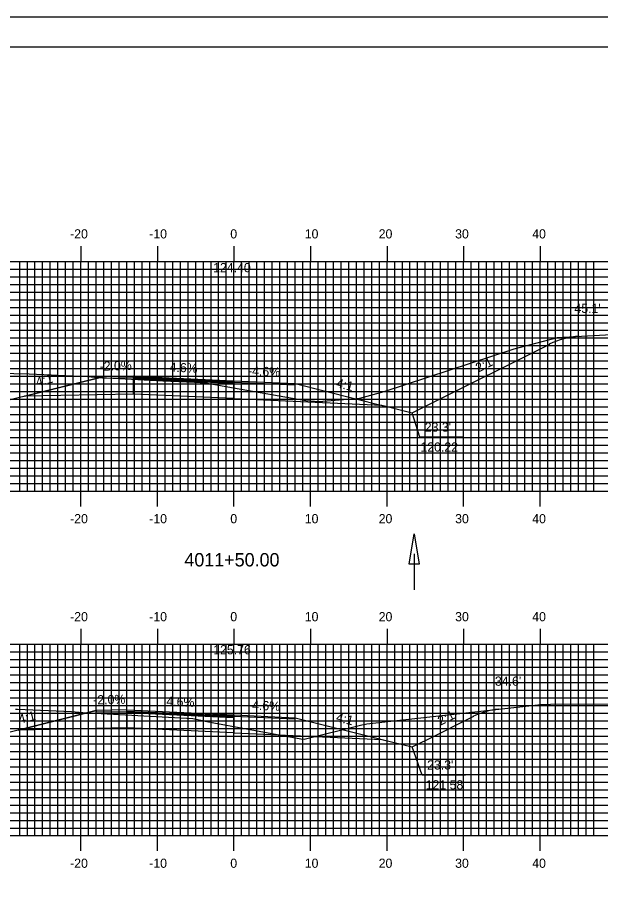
# Model space of a CAD drawing. Extents: x 852540 to 852884, y 364661 to 364881.
# Drawn here: x 852678 to 852754.2, y 364768.2 to 364881.3 of the extents above; entities that cross this region are included whole.
import ezdxf

# ---------------------------------------------------------------- set-up
doc = ezdxf.new("R2010")
doc.units = 0
for name, color, linetype in [('ANNOTATION', 7, 'Continuous'), ('BORDER', 7, 'Continuous'), ('D_Drainage_Ditch_Line', 7, 'Continuous'), ('D_Roadway_Centerline_Text', 7, 'Continuous'), ('D_Roadway_Edge_Shoulder', 7, 'Continuous'), ('D_Roadway_Edge_TW', 7, 'Continuous'), ('D_Roadway_Pavement', 7, 'Continuous'), ('D_Roadway_SlopeLines', 7, 'Continuous'), ('D_Roadway_SubGrade', 7, 'Continuous'), ('D_Text_Standard', 7, 'Continuous'), ('H_V ANNOTATION', 7, 'Continuous'), ('M_Roadway_Centerline', 7, 'Continuous'), ('MAJOR', 7, 'Continuous'), ('MINOR', 7, 'Continuous'), ('PLOT BOUNDARY', 7, 'Continuous'), ('S_Roadway_Centerline', 7, 'Continuous')]:
    doc.layers.add(name, color=color, linetype=linetype)

msp = doc.modelspace()

# ---------------------------------------------------------------- linework, layer by layer
at = {"layer": 'ANNOTATION'}
for points in [[(852725.57, 364830.59), (852729.57, 364829.59), (852731.57, 364830.59), (852747.53, 364838.57)], [(852736.23, 364826.4), (852730.54, 364826.4), (852729.57, 364829.59)], [(852725.57, 364786.95), (852729.57, 364785.95), (852731.57, 364786.95), (852737.6, 364789.97)], [(852736.54, 364782.29), (852730.85, 364782.29), (852729.57, 364785.95)]]:
    msp.add_lwpolyline(points, dxfattribs=at)
at = {"layer": 'BORDER'}
msp.add_lwpolyline([(852556.67, 364667.37), (852876.67, 364667.37), (852876.67, 364877.37), (852556.67, 364877.37)], close=True, dxfattribs=at)
at = {"layer": 'D_Drainage_Ditch_Line'}
msp.add_line((852729.82, 364811.16), (852729.82, 364806.46), dxfattribs=at)
msp.add_lwpolyline([(852730.47, 364809.84), (852729.16, 364809.84), (852729.82, 364813.78)], close=True, dxfattribs=at)
at = {"layer": 'D_Roadway_Edge_Shoulder'}
for points in [[(852693.13, 364834.39), (852689.13, 364834.31), (852689.13, 364834.14), (852693.13, 364834.21)], [(852692.28, 364790.79), (852688.28, 364790.71), (852688.28, 364790.54), (852692.28, 364790.6)]]:
    msp.add_lwpolyline(points, close=True, dxfattribs=at)
at = {"layer": 'D_Roadway_Edge_TW'}
for p, q in [((852706.27, 364833.79), (852714.27, 364833.42)), ((852706.27, 364790.14), (852714.27, 364789.78))]:
    msp.add_line(p, q, dxfattribs=at)
for points in [[(852693.13, 364834.39), (852706.27, 364833.79), (852706.27, 364833.62), (852693.13, 364834.21)], [(852692.28, 364790.79), (852706.27, 364790.14), (852706.27, 364789.98), (852692.28, 364790.6)]]:
    msp.add_lwpolyline(points, close=True, dxfattribs=at)
for points in [[(852706.27, 364833.62), (852714.27, 364833.25), (852714.27, 364833.42)], [(852706.27, 364789.98), (852714.27, 364789.61), (852714.27, 364789.78)]]:
    msp.add_lwpolyline(points, dxfattribs=at)
at = {"layer": 'D_Roadway_Pavement'}
for points in [[(852693.13, 364834.21), (852706.27, 364833.62), (852706.27, 364833.45), (852693.13, 364834.04)], [(852692.28, 364790.6), (852706.27, 364789.98), (852706.27, 364789.81), (852692.28, 364790.44)]]:
    msp.add_lwpolyline(points, close=True, dxfattribs=at)
for points in [[(852693.13, 364834.21), (852693.13, 364834.04)], [(852706.27, 364833.62), (852706.27, 364833.45)], [(852706.27, 364833.62), (852706.27, 364833.45)], [(852692.28, 364790.6), (852692.28, 364790.44)], [(852706.27, 364789.98), (852706.27, 364789.81)], [(852706.27, 364789.98), (852706.27, 364789.81)]]:
    msp.add_lwpolyline(points, dxfattribs=at)
at = {"layer": 'D_Roadway_SlopeLines'}
for points in [[(852689.13, 364834.31), (852674.91, 364830.76)], [(852714.27, 364833.42), (852725.8, 364830.53)], [(852688.28, 364790.71), (852674.06, 364787.15)], [(852714.27, 364789.78), (852725.8, 364786.89)]]:
    msp.add_lwpolyline(points, dxfattribs=at)
for centre, start in [((852751.94, 364829.6), 93.165), ((852741.96, 364780.97), 96.3976)]:
    msp.add_arc(centre, 10, start, 116.5651, dxfattribs=at)
at = {"layer": 'D_Roadway_SubGrade'}
for p, q in [((852706.27, 364831.45), (852725.57, 364830.59)), ((852706.27, 364787.81), (852725.57, 364786.95))]:
    msp.add_line(p, q, dxfattribs=at)
for points in [[(852693.13, 364832.04), (852678.91, 364831.76), (852689.13, 364834.31), (852689.13, 364834.14), (852693.13, 364834.21), (852693.13, 364834.04)], [(852693.13, 364834.04), (852706.27, 364833.45), (852706.27, 364831.45), (852693.13, 364832.04)], [(852692.28, 364788.44), (852678.06, 364788.15), (852688.28, 364790.71), (852688.28, 364790.54), (852692.28, 364790.6), (852692.28, 364790.44)], [(852692.28, 364790.44), (852706.27, 364789.81), (852706.27, 364787.81), (852692.28, 364788.44)]]:
    msp.add_lwpolyline(points, close=True, dxfattribs=at)
at = {"layer": 'MAJOR'}
for p, q in [((852686.27, 364851.37), (852686.27, 364849.37)), ((852696.27, 364851.37), (852696.27, 364849.37)), ((852706.27, 364851.37), (852706.27, 364849.37)), ((852716.27, 364851.37), (852716.27, 364849.37)), ((852726.27, 364851.37), (852726.27, 364849.37)), ((852736.27, 364851.37), (852736.27, 364849.37)), ((852746.27, 364851.37), (852746.27, 364849.37)), ((852566.27, 364849.37), (852846.27, 364849.37)), ((852566.27, 364849.37), (852846.27, 364849.37)), ((852686.27, 364819.37), (852686.27, 364849.37)), ((852696.27, 364819.37), (852696.27, 364849.37)), ((852706.27, 364819.37), (852706.27, 364849.37)), ((852716.27, 364819.37), (852716.27, 364849.37)), ((852726.27, 364819.37), (852726.27, 364849.37)), ((852736.27, 364819.37), (852736.27, 364849.37)), ((852746.27, 364819.37), (852746.27, 364849.37)), ((852566.27, 364844.37), (852846.27, 364844.37)), ((852566.27, 364839.37), (852846.27, 364839.37)), ((852566.27, 364834.37), (852846.27, 364834.37)), ((852566.27, 364829.37), (852846.27, 364829.37)), ((852566.27, 364824.37), (852846.27, 364824.37)), ((852566.27, 364819.37), (852846.27, 364819.37)), ((852566.27, 364819.37), (852846.27, 364819.37)), ((852686.27, 364817.37), (852686.27, 364819.37)), ((852696.27, 364817.37), (852696.27, 364819.37)), ((852706.27, 364817.37), (852706.27, 364819.37)), ((852716.27, 364817.37), (852716.27, 364819.37)), ((852726.27, 364817.37), (852726.27, 364819.37)), ((852736.27, 364817.37), (852736.27, 364819.37)), ((852746.27, 364817.37), (852746.27, 364819.37)), ((852686.27, 364801.37), (852686.27, 364799.37)), ((852696.27, 364801.37), (852696.27, 364799.37)), ((852706.27, 364801.37), (852706.27, 364799.37)), ((852716.27, 364801.37), (852716.27, 364799.37)), ((852726.27, 364801.37), (852726.27, 364799.37)), ((852736.27, 364801.37), (852736.27, 364799.37)), ((852746.27, 364801.37), (852746.27, 364799.37)), ((852566.27, 364799.37), (852846.27, 364799.37)), ((852566.27, 364799.37), (852846.27, 364799.37)), ((852686.27, 364774.37), (852686.27, 364799.37)), ((852696.27, 364774.37), (852696.27, 364799.37)), ((852706.27, 364774.37), (852706.27, 364799.37)), ((852716.27, 364774.37), (852716.27, 364799.37)), ((852726.27, 364774.37), (852726.27, 364799.37)), ((852736.27, 364774.37), (852736.27, 364799.37)), ((852746.27, 364774.37), (852746.27, 364799.37)), ((852566.27, 364794.37), (852846.27, 364794.37)), ((852566.27, 364789.37), (852846.27, 364789.37)), ((852566.27, 364784.37), (852846.27, 364784.37)), ((852566.27, 364779.37), (852846.27, 364779.37)), ((852566.27, 364774.37), (852846.27, 364774.37)), ((852566.27, 364774.37), (852846.27, 364774.37)), ((852686.27, 364772.37), (852686.27, 364774.37)), ((852696.27, 364772.37), (852696.27, 364774.37)), ((852706.27, 364772.37), (852706.27, 364774.37)), ((852716.27, 364772.37), (852716.27, 364774.37)), ((852726.27, 364772.37), (852726.27, 364774.37)), ((852736.27, 364772.37), (852736.27, 364774.37)), ((852746.27, 364772.37), (852746.27, 364774.37))]:
    msp.add_line(p, q, dxfattribs=at)
at = {"layer": 'MINOR'}
for p, q in [((852678.27, 364819.37), (852678.27, 364849.37)), ((852679.27, 364819.37), (852679.27, 364849.37)), ((852680.27, 364819.37), (852680.27, 364849.37)), ((852681.27, 364819.37), (852681.27, 364849.37)), ((852682.27, 364819.37), (852682.27, 364849.37)), ((852683.27, 364819.37), (852683.27, 364849.37)), ((852684.27, 364819.37), (852684.27, 364849.37)), ((852685.27, 364819.37), (852685.27, 364849.37)), ((852687.27, 364819.37), (852687.27, 364849.37)), ((852688.27, 364819.37), (852688.27, 364849.37)), ((852689.27, 364819.37), (852689.27, 364849.37)), ((852690.27, 364819.37), (852690.27, 364849.37)), ((852691.27, 364819.37), (852691.27, 364849.37)), ((852692.27, 364819.37), (852692.27, 364849.37)), ((852693.27, 364819.37), (852693.27, 364849.37)), ((852694.27, 364819.37), (852694.27, 364849.37)), ((852695.27, 364819.37), (852695.27, 364849.37)), ((852697.27, 364819.37), (852697.27, 364849.37)), ((852698.27, 364819.37), (852698.27, 364849.37)), ((852699.27, 364819.37), (852699.27, 364849.37)), ((852700.27, 364819.37), (852700.27, 364849.37)), ((852701.27, 364819.37), (852701.27, 364849.37)), ((852702.27, 364819.37), (852702.27, 364849.37)), ((852703.27, 364819.37), (852703.27, 364849.37)), ((852704.27, 364819.37), (852704.27, 364849.37)), ((852705.27, 364819.37), (852705.27, 364849.37)), ((852707.27, 364819.37), (852707.27, 364849.37)), ((852708.27, 364819.37), (852708.27, 364849.37)), ((852709.27, 364819.37), (852709.27, 364849.37)), ((852710.27, 364819.37), (852710.27, 364849.37)), ((852711.27, 364819.37), (852711.27, 364849.37)), ((852712.27, 364819.37), (852712.27, 364849.37)), ((852713.27, 364819.37), (852713.27, 364849.37)), ((852714.27, 364819.37), (852714.27, 364849.37)), ((852715.27, 364819.37), (852715.27, 364849.37)), ((852717.27, 364819.37), (852717.27, 364849.37)), ((852718.27, 364819.37), (852718.27, 364849.37)), ((852719.27, 364819.37), (852719.27, 364849.37)), ((852720.27, 364819.37), (852720.27, 364849.37)), ((852721.27, 364819.37), (852721.27, 364849.37)), ((852722.27, 364819.37), (852722.27, 364849.37)), ((852723.27, 364819.37), (852723.27, 364849.37)), ((852724.27, 364819.37), (852724.27, 364849.37)), ((852725.27, 364819.37), (852725.27, 364849.37)), ((852727.27, 364819.37), (852727.27, 364849.37)), ((852728.27, 364819.37), (852728.27, 364849.37)), ((852729.27, 364819.37), (852729.27, 364849.37)), ((852730.27, 364819.37), (852730.27, 364849.37)), ((852731.27, 364819.37), (852731.27, 364849.37)), ((852732.27, 364819.37), (852732.27, 364849.37)), ((852733.27, 364819.37), (852733.27, 364849.37)), ((852734.27, 364819.37), (852734.27, 364849.37)), ((852735.27, 364819.37), (852735.27, 364849.37)), ((852737.27, 364819.37), (852737.27, 364849.37)), ((852738.27, 364819.37), (852738.27, 364849.37)), ((852739.27, 364819.37), (852739.27, 364849.37)), ((852740.27, 364819.37), (852740.27, 364849.37)), ((852741.27, 364819.37), (852741.27, 364849.37)), ((852742.27, 364819.37), (852742.27, 364849.37)), ((852743.27, 364819.37), (852743.27, 364849.37)), ((852744.27, 364819.37), (852744.27, 364849.37)), ((852745.27, 364819.37), (852745.27, 364849.37)), ((852747.27, 364819.37), (852747.27, 364849.37)), ((852748.27, 364819.37), (852748.27, 364849.37)), ((852749.27, 364819.37), (852749.27, 364849.37)), ((852750.27, 364819.37), (852750.27, 364849.37)), ((852751.27, 364819.37), (852751.27, 364849.37)), ((852752.27, 364819.37), (852752.27, 364849.37)), ((852753.27, 364819.37), (852753.27, 364849.37)), ((852566.27, 364848.37), (852846.27, 364848.37)), ((852566.27, 364847.37), (852846.27, 364847.37)), ((852566.27, 364846.37), (852846.27, 364846.37)), ((852566.27, 364845.37), (852846.27, 364845.37)), ((852566.27, 364843.37), (852846.27, 364843.37)), ((852566.27, 364842.37), (852846.27, 364842.37)), ((852566.27, 364841.37), (852846.27, 364841.37)), ((852566.27, 364840.37), (852846.27, 364840.37)), ((852566.27, 364838.37), (852846.27, 364838.37)), ((852566.27, 364837.37), (852846.27, 364837.37)), ((852566.27, 364836.37), (852846.27, 364836.37)), ((852566.27, 364835.37), (852846.27, 364835.37)), ((852566.27, 364833.37), (852846.27, 364833.37)), ((852566.27, 364832.37), (852846.27, 364832.37)), ((852566.27, 364831.37), (852846.27, 364831.37)), ((852566.27, 364830.37), (852846.27, 364830.37)), ((852566.27, 364828.37), (852846.27, 364828.37)), ((852566.27, 364827.37), (852846.27, 364827.37)), ((852566.27, 364826.37), (852846.27, 364826.37)), ((852566.27, 364825.37), (852846.27, 364825.37)), ((852566.27, 364823.37), (852846.27, 364823.37)), ((852566.27, 364822.37), (852846.27, 364822.37)), ((852566.27, 364821.37), (852846.27, 364821.37)), ((852566.27, 364820.37), (852846.27, 364820.37)), ((852678.27, 364774.37), (852678.27, 364799.37)), ((852679.27, 364774.37), (852679.27, 364799.37)), ((852680.27, 364774.37), (852680.27, 364799.37)), ((852681.27, 364774.37), (852681.27, 364799.37)), ((852682.27, 364774.37), (852682.27, 364799.37)), ((852683.27, 364774.37), (852683.27, 364799.37)), ((852684.27, 364774.37), (852684.27, 364799.37)), ((852685.27, 364774.37), (852685.27, 364799.37)), ((852687.27, 364774.37), (852687.27, 364799.37)), ((852688.27, 364774.37), (852688.27, 364799.37)), ((852689.27, 364774.37), (852689.27, 364799.37)), ((852690.27, 364774.37), (852690.27, 364799.37)), ((852691.27, 364774.37), (852691.27, 364799.37)), ((852692.27, 364774.37), (852692.27, 364799.37)), ((852693.27, 364774.37), (852693.27, 364799.37)), ((852694.27, 364774.37), (852694.27, 364799.37)), ((852695.27, 364774.37), (852695.27, 364799.37)), ((852697.27, 364774.37), (852697.27, 364799.37)), ((852698.27, 364774.37), (852698.27, 364799.37)), ((852699.27, 364774.37), (852699.27, 364799.37)), ((852700.27, 364774.37), (852700.27, 364799.37)), ((852701.27, 364774.37), (852701.27, 364799.37)), ((852702.27, 364774.37), (852702.27, 364799.37)), ((852703.27, 364774.37), (852703.27, 364799.37)), ((852704.27, 364774.37), (852704.27, 364799.37)), ((852705.27, 364774.37), (852705.27, 364799.37)), ((852707.27, 364774.37), (852707.27, 364799.37)), ((852708.27, 364774.37), (852708.27, 364799.37)), ((852709.27, 364774.37), (852709.27, 364799.37)), ((852710.27, 364774.37), (852710.27, 364799.37)), ((852711.27, 364774.37), (852711.27, 364799.37)), ((852712.27, 364774.37), (852712.27, 364799.37)), ((852713.27, 364774.37), (852713.27, 364799.37)), ((852714.27, 364774.37), (852714.27, 364799.37)), ((852715.27, 364774.37), (852715.27, 364799.37)), ((852717.27, 364774.37), (852717.27, 364799.37)), ((852718.27, 364774.37), (852718.27, 364799.37)), ((852719.27, 364774.37), (852719.27, 364799.37)), ((852720.27, 364774.37), (852720.27, 364799.37)), ((852721.27, 364774.37), (852721.27, 364799.37)), ((852722.27, 364774.37), (852722.27, 364799.37)), ((852723.27, 364774.37), (852723.27, 364799.37)), ((852724.27, 364774.37), (852724.27, 364799.37)), ((852725.27, 364774.37), (852725.27, 364799.37)), ((852727.27, 364774.37), (852727.27, 364799.37)), ((852728.27, 364774.37), (852728.27, 364799.37)), ((852729.27, 364774.37), (852729.27, 364799.37)), ((852730.27, 364774.37), (852730.27, 364799.37)), ((852731.27, 364774.37), (852731.27, 364799.37)), ((852732.27, 364774.37), (852732.27, 364799.37)), ((852733.27, 364774.37), (852733.27, 364799.37)), ((852734.27, 364774.37), (852734.27, 364799.37)), ((852735.27, 364774.37), (852735.27, 364799.37)), ((852737.27, 364774.37), (852737.27, 364799.37)), ((852738.27, 364774.37), (852738.27, 364799.37)), ((852739.27, 364774.37), (852739.27, 364799.37)), ((852740.27, 364774.37), (852740.27, 364799.37)), ((852741.27, 364774.37), (852741.27, 364799.37)), ((852742.27, 364774.37), (852742.27, 364799.37)), ((852743.27, 364774.37), (852743.27, 364799.37)), ((852744.27, 364774.37), (852744.27, 364799.37)), ((852745.27, 364774.37), (852745.27, 364799.37)), ((852747.27, 364774.37), (852747.27, 364799.37)), ((852748.27, 364774.37), (852748.27, 364799.37)), ((852749.27, 364774.37), (852749.27, 364799.37)), ((852750.27, 364774.37), (852750.27, 364799.37)), ((852751.27, 364774.37), (852751.27, 364799.37)), ((852752.27, 364774.37), (852752.27, 364799.37)), ((852753.27, 364774.37), (852753.27, 364799.37)), ((852566.27, 364798.37), (852846.27, 364798.37)), ((852566.27, 364797.37), (852846.27, 364797.37)), ((852566.27, 364796.37), (852846.27, 364796.37)), ((852566.27, 364795.37), (852846.27, 364795.37)), ((852566.27, 364793.37), (852846.27, 364793.37)), ((852566.27, 364792.37), (852846.27, 364792.37)), ((852566.27, 364791.37), (852846.27, 364791.37)), ((852566.27, 364790.37), (852846.27, 364790.37)), ((852566.27, 364788.37), (852846.27, 364788.37)), ((852566.27, 364787.37), (852846.27, 364787.37)), ((852566.27, 364786.37), (852846.27, 364786.37)), ((852566.27, 364785.37), (852846.27, 364785.37)), ((852566.27, 364783.37), (852846.27, 364783.37)), ((852566.27, 364782.37), (852846.27, 364782.37)), ((852566.27, 364781.37), (852846.27, 364781.37)), ((852566.27, 364780.37), (852846.27, 364780.37)), ((852566.27, 364778.37), (852846.27, 364778.37)), ((852566.27, 364777.37), (852846.27, 364777.37)), ((852566.27, 364776.37), (852846.27, 364776.37)), ((852566.27, 364775.37), (852846.27, 364775.37))]:
    msp.add_line(p, q, dxfattribs=at)
at = {"layer": 'PLOT BOUNDARY'}
msp.add_lwpolyline([(852540.48, 364661.25), (852880.48, 364661.25), (852880.48, 364881.25), (852540.48, 364881.25)], close=True, dxfattribs=at)
at = {"layer": 'S_Roadway_Centerline'}
for points in [[(852675.45, 364834.77), (852679.5, 364834.7), (852687.12, 364834.35), (852688.05, 364834.26), (852688.78, 364834.21), (852696.99, 364833.79), (852701.1, 364833.58), (852702.55, 364833.53), (852706.22, 364832.86), (852715.66, 364831.21), (852717.35, 364831.06), (852722.73, 364831.49), (852725.89, 364832.36), (852742.9, 364837.95), (852748.53, 364839.42), (852767.3, 364840.46)], [(852677.72, 364790.88), (852677.99, 364790.87), (852685.04, 364790.57), (852686.53, 364790.46), (852698.51, 364789.81), (852700.88, 364789.68), (852702.17, 364789.4), (852702.2, 364789.39), (852702.52, 364789.34), (852703.66, 364789.12), (852715.01, 364787), (852715.46, 364786.98), (852722.97, 364788.84), (852723.46, 364788.95), (852723.65, 364788.98), (852746.35, 364791.52), (852747.63, 364791.55), (852758.74, 364791.59)]]:
    msp.add_lwpolyline(points, dxfattribs=at)

# ---------------------------------------------------------------- texts
at = {"layer": 'ANNOTATION'}
for s, rotation, p in [('2:1', 26.5651, (852738.21, 364834.85)), ('-2.0%', 1.1458, (852688.73, 364835.1)), ('4.6%', 357.3663, (852697.84, 364834.98)), ('-4.6%', 357.3663, (852708.09, 364834.5)), ('4:1', 14.0362, (852680.55, 364833.03)), ('4:1', 345.9638, (852719.54, 364832.96)), ('-2.0%', 1.1458, (852687.89, 364791.5)), ('4.6%', 357.3663, (852697.42, 364791.35)), ('-4.6%', 357.3663, (852708.09, 364790.86)), ('4:1', 14.0362, (852678.28, 364788.97)), ('4:1', 345.9638, (852719.54, 364789.32)), ('2:1', 26.5651, (852733.25, 364788.73))]:
    msp.add_text(s, height=1.2, rotation=rotation, dxfattribs=at).set_placement(p)
for s, p in [("23.3' ", (852731.2, 364827.13)), ('120.22', (852730.64, 364824.53)), ("23.3' ", (852731.51, 364783.01)), ('121.58', (852731.32, 364780.41))]:
    msp.add_text(s, height=1.2, dxfattribs=at).set_placement(p)
at = {"layer": 'D_Roadway_Centerline_Text'}
for s, p in [('124.40', (852703.55, 364847.96)), ('125.76', (852703.56, 364798.05))]:
    msp.add_text(s, height=1.2, dxfattribs=at).set_placement(p)
at = {"layer": 'D_Text_Standard'}
for s, p in [("45.1'", (852750.76, 364842.64)), ("34.6'", (852740.37, 364793.95))]:
    msp.add_text(s, height=1.2, dxfattribs=at).set_placement(p)
at = {"layer": 'H_V ANNOTATION'}
for s, height, p in [('-20', 1.2, (852684.86, 364852.37)), ('-10', 1.2, (852695.2, 364852.37)), ('0', 1.2, (852705.79, 364852.37)), ('10', 1.2, (852715.52, 364852.37)), ('20', 1.2, (852725.18, 364852.37)), ('30', 1.2, (852735.17, 364852.37)), ('40', 1.2, (852745.24, 364852.37)), ('-20', 1.2, (852684.86, 364815.17)), ('-10', 1.2, (852695.2, 364815.17)), ('0', 1.2, (852705.79, 364815.17)), ('10', 1.2, (852715.52, 364815.17)), ('20', 1.2, (852725.18, 364815.17)), ('30', 1.2, (852735.17, 364815.17)), ('40', 1.2, (852745.24, 364815.17)), ('4011+50.00', 1.75, (852699.79, 364809.53)), ('-20', 1.2, (852684.86, 364802.37)), ('-10', 1.2, (852695.2, 364802.37)), ('0', 1.2, (852705.79, 364802.37)), ('10', 1.2, (852715.52, 364802.37)), ('20', 1.2, (852725.18, 364802.37)), ('30', 1.2, (852735.17, 364802.37)), ('40', 1.2, (852745.24, 364802.37)), ('-20', 1.2, (852684.86, 364770.17)), ('-10', 1.2, (852695.2, 364770.17)), ('0', 1.2, (852705.79, 364770.17)), ('10', 1.2, (852715.52, 364770.17)), ('20', 1.2, (852725.18, 364770.17)), ('30', 1.2, (852735.17, 364770.17)), ('40', 1.2, (852745.24, 364770.17))]:
    msp.add_text(s, height=height, dxfattribs=at).set_placement(p)
at = {"layer": 'M_Roadway_Centerline'}
for s, p in [('C', (852687.11, 364834.35)), ('L', (852687.12, 364834.34)), ('C', (852685.03, 364790.57)), ('L', (852685.04, 364790.56))]:
    msp.add_text(s, height=0.0146, dxfattribs=at).set_placement(p)

doc.saveas('drawing.dxf')
